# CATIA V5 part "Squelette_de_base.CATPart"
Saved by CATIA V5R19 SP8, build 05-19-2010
Part number: Squelette de base
Publications: "Point.1", "Point.2", "Point.3", "Point.4", "Point.5", "Point.6", "Point.7", "Point.8", "Point.9", "Point.10", "Point.11", "Point.12", "Point.13", "Point.14", "Point.15", "Point.16", "Plan.2", "Plan.3", "Plan.1"
Bounding box of the stored display mesh (mm): x -37 to 0, y -30 to 30, z -1.25 to 1.25
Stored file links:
  C:\Users\ThinkMotion\Desktop\EU_thinkMotion\iao\IAO_MMS_Groupe3\ecartoux\projet_IAO_ecartoux\projet_IAO_ecartoux\griffe_d'une_camera_ecartoux\Squelette_de_base.CATPart
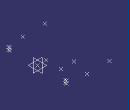
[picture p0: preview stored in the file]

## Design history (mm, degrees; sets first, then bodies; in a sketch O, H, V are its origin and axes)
Set1 "Set géométrique"
  Point1: (0, 0, 0)
  Point2: (-8, 0, 0)
  Point3: (-8, 14, 0)
  Point4: (-20, 14, 0)
  Plane1: type Offset, RefPlane xy-plane, Offset 0
  Point5: (-16, 30, 0)
  Point6: (-37, 30, 0)
  Point7: (-37, -30, 0)
  Point8: (-16, -30, 0)
  Point9: (0, -26, -1.25), relative to Point1
  Point10: (0, -26, 1.25)
  Point11: (0, 26, 1.25)
  Point12: (0, 26, -1.25)
  Point13: (0, 27, -1.25)
  Point14: (0, 27, 1.25)
  Point15: (0, -27, 1.25)
  Point16: (0, -27, -1.25)
  Plane2: type Offset, RefPlane yz-plane, Offset 0
  Plane3: type Offset, RefPlane zx-plane, Offset 0
Body1 (main body)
